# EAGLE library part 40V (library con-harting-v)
CONNECTOR
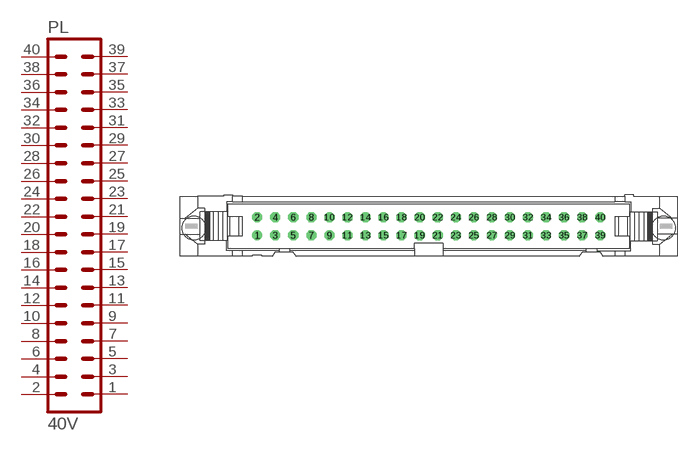
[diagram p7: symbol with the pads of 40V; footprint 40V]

Designator prefix PL

## 40V (OC_FARNELL: unknown; OC_NEWARK: unknown)  [40V]
1  1  pas
2  2  pas
3  3  pas
4  4  pas
5  5  pas
6  6  pas
7  7  pas
8  8  pas
9  9  pas
10  10  pas
11  11  pas
12  12  pas
13  13  pas
14  14  pas
15  15  pas
16  16  pas
17  17  pas
18  18  pas
19  19  pas
20  20  pas
21  21  pas
22  22  pas
23  23  pas
24  24  pas
25  25  pas
26  26  pas
27  27  pas
28  28  pas
29  29  pas
30  30  pas
31  31  pas
32  32  pas
33  33  pas
34  34  pas
35  35  pas
36  36  pas
37  37  pas
38  38  pas
39  39  pas
40  40  pas

## Footprint 40V (pad centres in mm)
CONNECTOR
drill 0.914 round: 1 -24.13,-1.27
drill 0.914 octagon: 2 -24.13,1.27; 3 -21.59,-1.27; 4 -21.59,1.27; 5 -19.05,-1.27; 6 -19.05,1.27; 7 -16.51,-1.27; 8 -16.51,1.27; 9 -13.97,-1.27; 10 -13.97,1.27; 11 -11.43,-1.27; 12 -11.43,1.27; 13 -8.89,-1.27; 14 -8.89,1.27; 15 -6.35,-1.27; 16 -6.35,1.27; 17 -3.81,-1.27; 18 -3.81,1.27; 19 -1.27,-1.27; 20 -1.27,1.27; 21 1.27,-1.27; 22 1.27,1.27; 23 3.81,-1.27; 24 3.81,1.27; 25 6.35,-1.27; 26 6.35,1.27; 27 8.89,-1.27; 28 8.89,1.27; 29 11.43,-1.27; 30 11.43,1.27; 31 13.97,-1.27; 32 13.97,1.27; 33 16.51,-1.27; 34 16.51,1.27; 35 19.05,-1.27; 36 19.05,1.27; 37 21.59,-1.27; 38 21.59,1.27; 39 24.13,-1.27; 40 24.13,1.27
hole 3.302 at 33.02,-0.254
hole 3.302 at -33.02,-0.254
